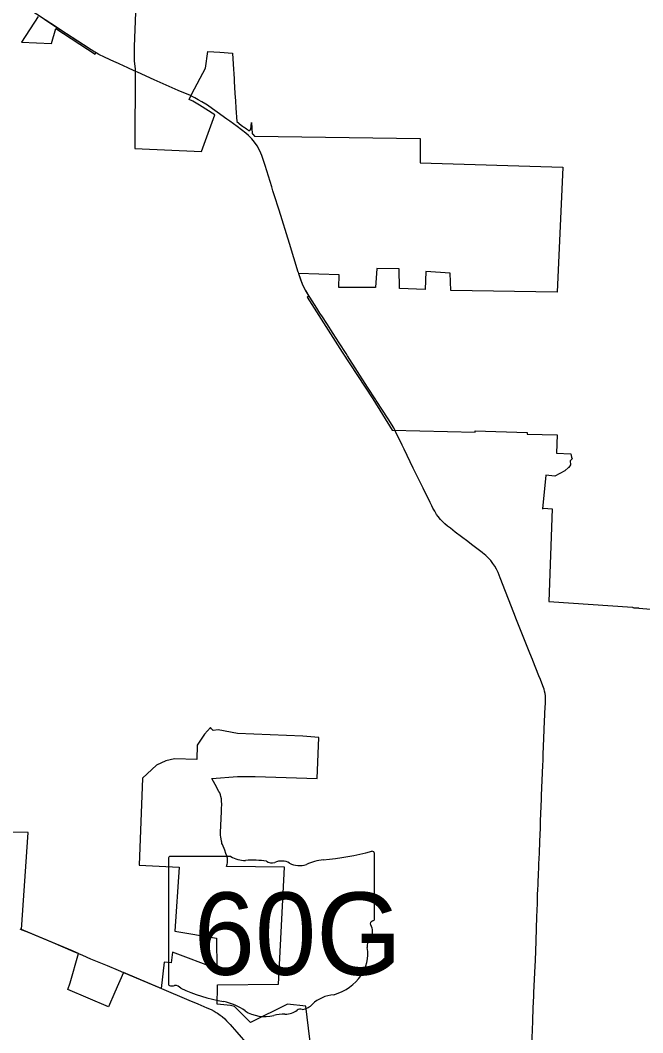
# Model space of a CAD drawing. Extents: x 2015843 to 2287843, y 623733 to 799733.
# Drawn here: x 2113699 to 2122171, y 708036 to 721811 of the extents above; entities that cross this region are included whole.
import ezdxf

# ---------------------------------------------------------------- set-up
doc = ezdxf.new("R2010")
doc.units = 0
for name, color, linetype in [('GM_X_Corporation', 7, 'Continuous'), ('GM_X_State_Route', 7, 'Continuous'), ('GM_X_State_Shield', 7, 'Continuous')]:
    doc.layers.add(name, color=color, linetype=linetype)

msp = doc.modelspace()

# ---------------------------------------------------------------- linework, layer by layer
at = {"layer": 'GM_X_Corporation'}
for points in [[(2113944, 721860), (2113716, 721511), (2114123, 721496), (2114185, 721700), (2114720, 721351), (2114727, 721369), (2114700, 721385), (2114629, 721429), (2114244, 721680), (2114185, 721718), (2114034, 721817)], [(2115267, 721917), (2115247, 721453), (2115250, 721256), (2115262, 721151), (2115258, 720064), (2116165, 720024), (2116346, 720522), (2116138, 720657), (2116048, 720709), (2115997, 720734), (2116032, 720809), (2116221, 721159), (2116250, 721385), (2116417, 721375), (2116587, 721365), (2116597, 721215), (2116609, 721016), (2116611, 720980), (2116621, 720816), (2116627, 720716), (2116634, 720617), (2116648, 720432), (2116704, 720382), (2116722, 720371), (2116735, 720363), (2116747, 720355), (2116759, 720346), (2116779, 720332), (2116790, 720323), (2116799, 720316), (2116811, 720306), (2116837, 720328), (2116846, 720418), (2116855, 720267), (2116862, 720260), (2116888, 720234), (2119140, 720203), (2119143, 719869), (2121083, 719811), (2121005, 718111), (2119557, 718133), (2119549, 718370), (2119220, 718394), (2119211, 718149), (2118858, 718161), (2118856, 718429), (2118550, 718434), (2118533, 718177), (2118034, 718173), (2118038, 718348), (2117484, 718365), (2117511, 718285), (2117536, 718223), (2117558, 718177), (2117581, 718133), (2117624, 718057), (2117602, 718042), (2118078, 717293), (2118498, 716659), (2118759, 716233), (2119890, 716205), (2119891, 716224), (2120598, 716203), (2120599, 716180), (2121007, 716171), (2120995, 715919), (2121193, 715912), (2121202, 715866), (2121208, 715845), (2121182, 715819), (2121188, 715764), (2121163, 715726), (2121160, 715728), (2121109, 715682), (2120973, 715610), (2120853, 715623), (2120806, 715164), (2120820, 715174), (2120939, 715164), (2120891, 713903), (2122033, 713824), (2122036, 713822), (2122039, 713820), (2122048, 713817), (2122057, 713817), (2122094, 713816), (2122111, 713815), (2122116, 713813), (2122120, 713811), (2122276, 713799)], [(2117717, 707312), (2117587, 708398), (2117336, 708426), (2116831, 708177), (2116615, 708391), (2116562, 708407), (2116380, 708423), (2116380, 708495), (2116383, 708580), (2116385, 708686), (2117212, 708696), (2117296, 710288), (2116504, 710298), (2116514, 710329), (2116518, 710346), (2116520, 710362), (2116520, 710379), (2116519, 710396), (2116517, 710412), (2116510, 710436), (2116508, 710444), (2116498, 710475), (2116481, 710522), (2116450, 710597), (2116444, 710612), (2116440, 710628), (2116437, 710640), (2116437, 710643), (2116431, 710672), (2116429, 710695), (2116426, 710724), (2116426, 710758), (2116438, 711046), (2116439, 711082), (2116442, 711147), (2116439, 711188), (2116437, 711217), (2116430, 711251), (2116422, 711274), (2116413, 711299), (2116403, 711318), (2116352, 711413), (2116304, 711497), (2116657, 711524), (2116895, 711523), (2117738, 711497), (2117760, 712053), (2117545, 712072), (2116654, 712108), (2116393, 712156), (2116322, 712146), (2116303, 712169), (2116286, 712188), (2116208, 712100), (2116107, 711947), (2116101, 711754), (2115796, 711763), (2115682, 711736), (2115554, 711675), (2115361, 711501), (2115315, 710315), (2115863, 710289), (2115801, 709417), (2116370, 709322), (2116376, 708906), (2115771, 709132), (2115752, 708986), (2115656, 708995), (2115618, 708637), (2115102, 708855), (2114986, 708589), (2114899, 708390), (2114348, 708622), (2114376, 708715), (2114493, 709112), (2114408, 709148), (2114136, 709263), (2113803, 709404), (2113717, 709439), (2113805, 710762), (2113390, 710770)]]:
    msp.add_lwpolyline(points, dxfattribs=at)
at = {"layer": 'GM_X_State_Route'}
for p, q in [((2118804, 716217), (2118782, 716264)), ((2120814, 711741), (2120817, 711823)), ((2115106, 708854), (2115623, 708636))]:
    msp.add_line(p, q, dxfattribs=at)
for points in [[(2114719, 721375), (2114705, 721383), (2114635, 721428), (2114250, 721678), (2114190, 721717), (2114039, 721816), (2113699, 722037)], [(2115293, 721103), (2115249, 721123), (2115165, 721164), (2115046, 721217), (2114997, 721239), (2114980, 721247), (2114844, 721307), (2114769, 721347), (2114732, 721368), (2114719, 721375)], [(2116019, 720782), (2116014, 720785), (2115848, 720856), (2115520, 721002), (2115293, 721103)], [(2116549, 720436), (2116510, 720463), (2116378, 720560), (2116232, 720663), (2116223, 720669), (2116170, 720701), (2116122, 720729), (2116074, 720755), (2116019, 720782)], [(2117030, 719837), (2116987, 719969), (2116961, 720036), (2116922, 720101), (2116888, 720153), (2116852, 720196), (2116839, 720211), (2116805, 720245), (2116768, 720276), (2116652, 720364), (2116549, 720436)], [(2117484, 718377), (2117483, 718382), (2117362, 718772), (2117222, 719225), (2117155, 719437), (2117138, 719491), (2117122, 719544), (2117079, 719691), (2117030, 719837)], [(2117638, 718042), (2117630, 718056), (2117587, 718131), (2117563, 718176), (2117542, 718221), (2117517, 718283), (2117489, 718363), (2117484, 718377)], [(2117811, 717775), (2117776, 717827), (2117734, 717892), (2117638, 718042)], [(2118782, 716264), (2118704, 716389), (2118543, 716638), (2118536, 716647), (2118424, 716820), (2118154, 717245), (2118132, 717278), (2118039, 717420), (2117956, 717550), (2117869, 717687), (2117811, 717775)], [(2120668, 713116), (2120635, 713198), (2120534, 713449), (2120489, 713564), (2120453, 713653), (2120414, 713751), (2120232, 714223), (2120202, 714298), (2120181, 714341), (2120157, 714383), (2120131, 714422), (2120101, 714460), (2120069, 714496), (2120035, 714528), (2119991, 714565), (2119985, 714570), (2119842, 714679), (2119789, 714719), (2119619, 714848), (2119552, 714899), (2119515, 714928), (2119476, 714961), (2119440, 714996), (2119417, 715020), (2119385, 715060), (2119365, 715088), (2119339, 715130), (2119314, 715174), (2119299, 715203), (2119277, 715248), (2119182, 715444), (2119155, 715499), (2119048, 715718), (2118923, 715974), (2118896, 716029), (2118804, 716217)], [(2120817, 711823), (2120826, 712044), (2120834, 712273), (2120838, 712360), (2120840, 712388), (2120846, 712523), (2120846, 712532), (2120847, 712571), (2120845, 712619), (2120841, 712650), (2120835, 712681), (2120827, 712712), (2120820, 712732), (2120812, 712757), (2120778, 712841), (2120757, 712893), (2120674, 713101), (2120668, 713116)], [(2120731, 709613), (2120736, 709792), (2120740, 709904), (2120744, 709999), (2120746, 710034), (2120748, 710099), (2120749, 710123), (2120750, 710149), (2120758, 710331), (2120761, 710411), (2120764, 710476), (2120770, 710640), (2120777, 710819), (2120781, 710918), (2120791, 711213), (2120793, 711263), (2120811, 711678), (2120814, 711741)], [(2120715, 709144), (2120720, 709284), (2120720, 709292), (2120731, 709613)], [(2113695, 709448), (2113722, 709437), (2113733, 709433)], [(2113733, 709433), (2113808, 709402), (2114141, 709262), (2114413, 709147), (2114492, 709113)], [(2114492, 709113), (2114546, 709090), (2114655, 709043), (2114882, 708949), (2115033, 708885), (2115106, 708854)], [(2120661, 707885), (2120666, 707982), (2120669, 708064), (2120674, 708205), (2120675, 708227), (2120685, 708473), (2120687, 708515), (2120690, 708584), (2120707, 708940), (2120710, 709018), (2120710, 709022), (2120715, 709144)], [(2115623, 708636), (2115994, 708477), (2116115, 708427)], [(2116115, 708427), (2116236, 708376), (2116296, 708350), (2116339, 708328), (2116365, 708313), (2116381, 708303), (2116421, 708276), (2116446, 708255), (2116482, 708223), (2116505, 708200), (2116539, 708165), (2116555, 708146)], [(2116555, 708146), (2116582, 708117), (2116646, 708042), (2117094, 707525), (2117240, 707357), (2117307, 707283), (2117320, 707267)]]:
    msp.add_lwpolyline(points, dxfattribs=at)
at = {"layer": 'GM_X_State_Shield'}
for p, q in [((2115716, 710405), (2115716, 708704)), ((2116564, 710434), (2115744, 710434)), ((2118518, 709587), (2118518, 710477)), ((2118518, 709587), (2118518, 709587))]:
    msp.add_line(p, q, dxfattribs=at)
for centre, major_axis, start_param, end_param in [((2115748, 710409), (32.5, 0), 1.712693, 3.28349), ((2116760, 710632), (315, 0), 4.042523, 4.731795), ((2117520, 712754), (2971, 0), 4.814394, 5.042369), ((2118487, 710480), (31.2, 0), 6.141152, 7.989035), ((2116864, 709479), (1130, 0), 1.404758, 1.657858), ((2117121, 710418), (90.8, 0), 3.836095, 5.185415), ((2117254, 710221), (189, 0), 0.950623, 2.079405), ((2117498, 710491), (227, 0), 4.081561, 5.145723), ((2117899, 709915), (598, 0), 1.699011, 2.107814), ((2118485, 709583), (33.4, 0), 5.05454, 6.418171), ((2118511, 709521), (48.3, 0), 1.883978, 3.671073), ((2118204, 709409), (290, 0), 5.934695, 6.695948), ((2118630, 709214), (211, 0), 2.387724, 3.262537), ((2117686, 709101), (743, 0), 5.101752, 6.440018), ((2115749, 708700), (32.7, 0), 3.00124, 4.508301), ((2115754, 708874), (250, 0), 4.665946, 4.897461), ((2115805, 708606), (90.1, 0), 0.519207, 1.627899), ((2116942, 710134), (2146, 0), 4.195997, 4.488961), ((2118000, 708226), (407, 0), 1.647645, 2.488434), ((2116303, 707940), (671, 0), 0.823519, 1.323587), ((2117029, 708597), (426, 0), 4.026481, 4.996735), ((2117306, 708470), (227, 0), 4.691044, 5.507374), ((2117511, 708305), (63.9, 0), 1.147584, 2.315152), ((2117484, 708539), (240, 0), 4.937069, 5.64225), ((2117275, 708009), (350, 0), 1.495662, 1.94098)]:
    msp.add_ellipse(centre, major_axis=major_axis, ratio=0.8, start_param=start_param, end_param=end_param, dxfattribs=at)

# ---------------------------------------------------------------- texts
msp.add_text('60G', height=1120.7, dxfattribs=at).set_placement((2116060, 708824))

doc.saveas('drawing.dxf')
